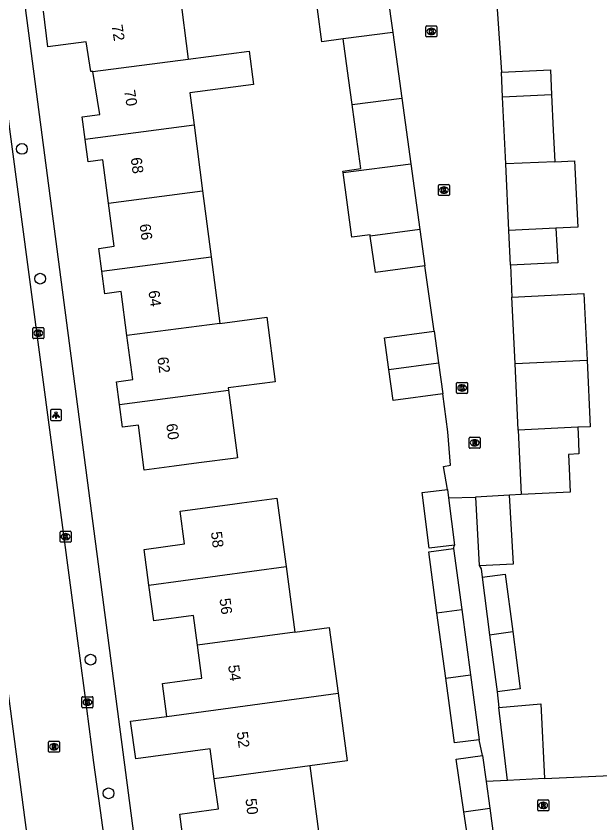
# Model space of a CAD drawing. Extents: x 161084 to 161928, y 385355 to 386522.
# Drawn here: x 161239.4 to 161292.4, y 386038.7 to 386112 of the extents above; entities that cross this region are included whole.
import ezdxf

# ---------------------------------------------------------------- set-up
doc = ezdxf.new("R2010")
doc.units = 0
for name, color, linetype in [('IMGEO_Boom', 7, 'Continuous'), ('IMGEO_Kolk', 7, 'Continuous'), ('IMGEO_Lichtpunt', 7, 'Continuous'), ('IMGEO_Pand', 7, 'Continuous'), ('IMGEO_Pand_nummerreeks', 7, 'Continuous'), ('IMGEO_Rijbaan_lokaal_open', 7, 'Continuous'), ('IMGEO_Rioolput', 7, 'Continuous'), ('IMGEO_Voetpad_open', 7, 'Continuous')]:
    doc.layers.add(name, color=color, linetype=linetype)

msp = doc.modelspace()

# ---------------------------------------------------------------- linework, layer by layer
at = {"layer": 'IMGEO_Boom'}
for centre in [(161239.881, 386099.938), (161241.543, 386088.142), (161246.128, 386053.505), (161247.762, 386041.354)]:
    msp.add_circle(centre, 0.489, dxfattribs=at)
at = {"layer": 'IMGEO_Kolk'}
for p, q in [((161276.692, 386111.123), (161277.544, 386111.123)), ((161276.617, 386110.197), (161276.617, 386111.049)), ((161277.128, 386110.343), (161277.103, 386110.343)), ((161277.105, 386110.903), (161277.13, 386110.903)), ((161277.618, 386111.049), (161277.618, 386110.197)), ((161277.544, 386110.123), (161276.692, 386110.123)), ((161277.763, 386095.772), (161277.763, 386096.624)), ((161277.838, 386096.698), (161278.69, 386096.698)), ((161278.251, 386096.478), (161278.276, 386096.478)), ((161278.764, 386096.624), (161278.764, 386095.772)), ((161278.69, 386095.698), (161277.838, 386095.698)), ((161278.274, 386095.918), (161278.249, 386095.918)), ((161240.877, 386082.763), (161240.877, 386083.615)), ((161240.952, 386083.689), (161241.804, 386083.689)), ((161241.365, 386083.469), (161241.39, 386083.469)), ((161241.878, 386083.615), (161241.878, 386082.763)), ((161241.804, 386082.689), (161240.952, 386082.689)), ((161241.388, 386082.909), (161241.363, 386082.909)), ((161279.415, 386077.779), (161279.415, 386078.631)), ((161279.49, 386078.705), (161280.342, 386078.705)), ((161279.903, 386078.485), (161279.928, 386078.485)), ((161280.416, 386078.631), (161280.416, 386077.779)), ((161280.342, 386077.705), (161279.49, 386077.705)), ((161279.926, 386077.925), (161279.901, 386077.925)), ((161243.352, 386064.258), (161243.352, 386065.11)), ((161243.427, 386065.184), (161244.279, 386065.184)), ((161243.84, 386064.964), (161243.865, 386064.964)), ((161244.353, 386065.11), (161244.353, 386064.258)), ((161244.279, 386064.184), (161243.427, 386064.184)), ((161243.863, 386064.404), (161243.838, 386064.404)), ((161245.342, 386049.207), (161245.342, 386050.059)), ((161245.417, 386050.133), (161246.269, 386050.133)), ((161245.83, 386049.913), (161245.855, 386049.913)), ((161246.343, 386050.059), (161246.343, 386049.207)), ((161246.269, 386049.133), (161245.417, 386049.133)), ((161245.853, 386049.353), (161245.828, 386049.353))]:
    msp.add_line(p, q, dxfattribs=at)
for points in [[(161276.692, 386111.123), (161277.544, 386111.123)], [(161276.617, 386110.197), (161276.617, 386111.049)], [(161276.938, 386110.823), (161277.061, 386110.823), (161277.061, 386110.672), (161277.191, 386110.823), (161277.355, 386110.823), (161277.209, 386110.672), (161277.362, 386110.423), (161277.21, 386110.423), (161277.125, 386110.587), (161277.061, 386110.52), (161277.061, 386110.423), (161276.938, 386110.423), (161276.938, 386110.823)], [(161277.618, 386111.049), (161277.618, 386110.197)], [(161277.544, 386110.123), (161276.692, 386110.123)], [(161277.763, 386095.772), (161277.763, 386096.624)], [(161277.838, 386096.698), (161278.69, 386096.698)], [(161278.764, 386096.624), (161278.764, 386095.772)], [(161278.69, 386095.698), (161277.838, 386095.698)], [(161278.084, 386096.398), (161278.207, 386096.398), (161278.207, 386096.247), (161278.337, 386096.398), (161278.501, 386096.398), (161278.355, 386096.247), (161278.508, 386095.998), (161278.356, 386095.998), (161278.271, 386096.162), (161278.207, 386096.095), (161278.207, 386095.998), (161278.084, 386095.998), (161278.084, 386096.398)], [(161240.877, 386082.763), (161240.877, 386083.615)], [(161240.952, 386083.689), (161241.804, 386083.689)], [(161241.198, 386083.389), (161241.321, 386083.389), (161241.321, 386083.238), (161241.451, 386083.389), (161241.615, 386083.389), (161241.469, 386083.238), (161241.622, 386082.989), (161241.47, 386082.989), (161241.385, 386083.153), (161241.321, 386083.086), (161241.321, 386082.989), (161241.198, 386082.989), (161241.198, 386083.389)], [(161241.878, 386083.615), (161241.878, 386082.763)], [(161241.804, 386082.689), (161240.952, 386082.689)], [(161279.415, 386077.779), (161279.415, 386078.631)], [(161279.49, 386078.705), (161280.342, 386078.705)], [(161279.736, 386078.405), (161279.859, 386078.405), (161279.859, 386078.254), (161279.989, 386078.405), (161280.153, 386078.405), (161280.007, 386078.254), (161280.16, 386078.005), (161280.008, 386078.005), (161279.923, 386078.169), (161279.859, 386078.102), (161279.859, 386078.005), (161279.736, 386078.005), (161279.736, 386078.405)], [(161280.416, 386078.631), (161280.416, 386077.779)], [(161280.342, 386077.705), (161279.49, 386077.705)], [(161243.352, 386064.258), (161243.352, 386065.11)], [(161243.427, 386065.184), (161244.279, 386065.184)], [(161243.673, 386064.884), (161243.796, 386064.884), (161243.796, 386064.733), (161243.926, 386064.884), (161244.09, 386064.884), (161243.944, 386064.733), (161244.097, 386064.484), (161243.945, 386064.484), (161243.86, 386064.648), (161243.796, 386064.581), (161243.796, 386064.484), (161243.673, 386064.484), (161243.673, 386064.884)], [(161244.353, 386065.11), (161244.353, 386064.258)], [(161244.279, 386064.184), (161243.427, 386064.184)], [(161245.342, 386049.207), (161245.342, 386050.059)], [(161245.417, 386050.133), (161246.269, 386050.133)], [(161245.663, 386049.833), (161245.786, 386049.833), (161245.786, 386049.682), (161245.916, 386049.833), (161246.08, 386049.833), (161245.934, 386049.682), (161246.087, 386049.433), (161245.935, 386049.433), (161245.85, 386049.597), (161245.786, 386049.53), (161245.786, 386049.433), (161245.663, 386049.433), (161245.663, 386049.833)], [(161246.343, 386050.059), (161246.343, 386049.207)], [(161246.269, 386049.133), (161245.417, 386049.133)]]:
    msp.add_lwpolyline(points, dxfattribs=at)
for centre, start, end in [((161276.694, 386111.047), 91.55205, 178.44795), ((161276.694, 386111.047), 91.55205, 178.44795), ((161277.542, 386111.047), 1.55205, 88.44795), ((161277.542, 386111.047), 1.55205, 88.44795), ((161276.694, 386110.199), 181.55205, 268.44795), ((161276.694, 386110.199), 181.55205, 268.44795), ((161277.542, 386110.199), 271.55205, 358.44795), ((161277.542, 386110.199), 271.55205, 358.44795), ((161277.84, 386096.622), 91.55205, 178.44795), ((161277.84, 386096.622), 91.55205, 178.44795), ((161278.688, 386096.622), 1.55205, 88.44795), ((161278.688, 386096.622), 1.55205, 88.44795), ((161277.84, 386095.774), 181.55205, 268.44795), ((161277.84, 386095.774), 181.55205, 268.44795), ((161278.688, 386095.774), 271.55205, 358.44795), ((161278.688, 386095.774), 271.55205, 358.44795), ((161240.954, 386083.613), 91.55205, 178.44795), ((161240.954, 386083.613), 91.55205, 178.44795), ((161241.802, 386083.613), 1.55205, 88.44795), ((161241.802, 386083.613), 1.55205, 88.44795), ((161240.954, 386082.765), 181.55205, 268.44795), ((161240.954, 386082.765), 181.55205, 268.44795), ((161241.802, 386082.765), 271.55205, 358.44795), ((161241.802, 386082.765), 271.55205, 358.44795), ((161279.492, 386078.629), 91.55205, 178.44795), ((161279.492, 386078.629), 91.55205, 178.44795), ((161280.34, 386078.629), 1.55205, 88.44795), ((161280.34, 386078.629), 1.55205, 88.44795), ((161279.492, 386077.781), 181.55205, 268.44795), ((161279.492, 386077.781), 181.55205, 268.44795), ((161280.34, 386077.781), 271.55205, 358.44795), ((161280.34, 386077.781), 271.55205, 358.44795), ((161243.429, 386065.108), 91.55205, 178.44795), ((161243.429, 386065.108), 91.55205, 178.44795), ((161244.277, 386065.108), 1.55205, 88.44795), ((161244.277, 386065.108), 1.55205, 88.44795), ((161243.429, 386064.26), 181.55205, 268.44795), ((161243.429, 386064.26), 181.55205, 268.44795), ((161244.277, 386064.26), 271.55205, 358.44795), ((161244.277, 386064.26), 271.55205, 358.44795), ((161245.419, 386050.057), 91.55205, 178.44795), ((161245.419, 386050.057), 91.55205, 178.44795), ((161246.267, 386050.057), 1.55205, 88.44795), ((161246.267, 386050.057), 1.55205, 88.44795), ((161245.419, 386049.209), 181.55205, 268.44795), ((161245.419, 386049.209), 181.55205, 268.44795), ((161246.267, 386049.209), 271.55205, 358.44795), ((161246.267, 386049.209), 271.55205, 358.44795)]:
    msp.add_arc(centre, 0.0765, start, end, dxfattribs=at)
for centre, major_axis, ratio, start_param, end_param in [((161277.104, 386110.623), (-0.387, 0.002), 0.722429, 4.712389, 7.853982), ((161277.129, 386110.623), (-0.39, 0.002), 0.717154, 1.570796, 4.712389), ((161278.25, 386096.198), (-0.387, 0.002), 0.722429, 4.712389, 7.853982), ((161278.275, 386096.198), (-0.39, 0.002), 0.717154, 1.570796, 4.712389), ((161241.364, 386083.189), (-0.387, 0.002), 0.722429, 4.712389, 7.853982), ((161241.389, 386083.189), (-0.39, 0.002), 0.717154, 1.570796, 4.712389), ((161279.902, 386078.205), (-0.387, 0.002), 0.722429, 4.712389, 7.853982), ((161279.927, 386078.205), (-0.39, 0.002), 0.717154, 1.570796, 4.712389), ((161243.839, 386064.684), (-0.387, 0.002), 0.722429, 4.712389, 7.853982), ((161243.864, 386064.684), (-0.39, 0.002), 0.717154, 1.570796, 4.712389), ((161245.829, 386049.633), (-0.387, 0.002), 0.722429, 4.712389, 7.853982), ((161245.854, 386049.633), (-0.39, 0.002), 0.717154, 1.570796, 4.712389)]:
    msp.add_ellipse(centre, major_axis=major_axis, ratio=ratio, start_param=start_param, end_param=end_param, dxfattribs=at)
at = {"layer": 'IMGEO_Lichtpunt'}
for p, q in [((161242.475, 386076.141), (161242.475, 386075.334)), ((161242.475, 386076.141), (161242.475, 386075.334)), ((161243.377, 386076.236), (161242.569, 386076.236)), ((161243.377, 386076.236), (161242.569, 386076.236)), ((161243.471, 386075.334), (161243.471, 386076.141)), ((161243.471, 386075.334), (161243.471, 386076.141)), ((161242.569, 386075.24), (161243.377, 386075.24)), ((161242.569, 386075.24), (161243.377, 386075.24))]:
    msp.add_line(p, q, dxfattribs=at)
for points in [[(161242.849, 386075.805), (161242.888, 386075.777), (161242.7, 386075.515), (161242.662, 386075.542), (161242.849, 386075.805)], [(161242.951, 386075.757), (161242.998, 386075.757), (161242.998, 386075.435), (161242.951, 386075.435), (161242.951, 386075.757)], [(161243.061, 386075.777), (161243.099, 386075.804), (161243.286, 386075.542), (161243.247, 386075.514), (161243.061, 386075.777)]]:
    msp.add_lwpolyline(points, dxfattribs=at)
msp.add_circle((161242.974, 386075.939), 0.0994, dxfattribs=at)
for centre, start, end in [((161242.569, 386076.141), 90, 180), ((161242.569, 386076.141), 90, 180), ((161243.377, 386076.141), 0, 90), ((161243.377, 386076.141), 0, 90), ((161242.569, 386075.334), 180, 270), ((161242.569, 386075.334), 180, 270), ((161243.377, 386075.334), 270, 0), ((161243.377, 386075.334), 270, 360)]:
    msp.add_arc(centre, 0.0946, start, end, dxfattribs=at)
at = {"layer": 'IMGEO_Pand'}
for points in [[(161272.778, 386116.48), (161273.124, 386113.984), (161273.603, 386110.526)], [(161269.087, 386109.933), (161267.146, 386109.681), (161266.372, 386115.646)], [(161254.234, 386114.065), (161255.011, 386108.105)], [(161246.334, 386106.975), (161246.15, 386106.977), (161245.713, 386109.678), (161242.252, 386109.227), (161241.832, 386112.45)], [(161273.603, 386110.526), (161269.087, 386109.933)], [(161273.603, 386110.526), (161274.429, 386104.558)], [(161269.913, 386103.97), (161269.58, 386106.378), (161269.087, 386109.933)], [(161255.011, 386108.105), (161260.555, 386108.828), (161260.952, 386105.784), (161255.151, 386105.028), (161255.533, 386102.097)], [(161246.334, 386106.975), (161255.011, 386108.105)], [(161245.629, 386100.807), (161245.358, 386102.86), (161246.965, 386103.072), (161246.334, 386106.975)], [(161283.492, 386106.92), (161287.952, 386107.128), (161288.058, 386104.844)], [(161283.599, 386104.63), (161283.492, 386106.92)], [(161269.913, 386103.97), (161274.429, 386104.558)], [(161274.429, 386104.558), (161275.255, 386098.592)], [(161288.058, 386104.844), (161283.599, 386104.63)], [(161283.881, 386098.577), (161283.599, 386104.63)], [(161288.058, 386104.844), (161288.208, 386101.632), (161288.342, 386098.766)], [(161269.083, 386097.788), (161269.065, 386097.922), (161270.719, 386098.151), (161270.348, 386100.831), (161269.913, 386103.97)], [(161255.533, 386102.097), (161245.629, 386100.807)], [(161255.533, 386102.097), (161256.312, 386096.124)], [(161247.763, 386095.01), (161247.247, 386098.933), (161245.899, 386098.755), (161245.629, 386100.807)], [(161288.342, 386098.766), (161283.881, 386098.577)], [(161288.342, 386098.766), (161290.147, 386098.851), (161290.429, 386092.822), (161288.438, 386092.728)], [(161269.083, 386097.788), (161275.255, 386098.592)], [(161275.255, 386098.592), (161276.084, 386092.604)], [(161284.163, 386092.522), (161283.881, 386098.577)], [(161271.568, 386092.015), (161271.552, 386092.131), (161269.897, 386091.902), (161269.083, 386097.788)], [(161247.763, 386095.01), (161256.312, 386096.124)], [(161256.312, 386096.124), (161257.094, 386090.131)], [(161247.14, 386088.835), (161246.868, 386090.9), (161248.28, 386091.086), (161247.763, 386095.01)], [(161276.084, 386092.604), (161271.568, 386092.015)], [(161276.539, 386089.321), (161272.027, 386088.696), (161271.568, 386092.015)], [(161276.084, 386092.604), (161276.539, 386089.321)], [(161288.438, 386092.728), (161284.163, 386092.522)], [(161284.31, 386089.371), (161284.163, 386092.522)], [(161288.438, 386092.728), (161288.611, 386089.572), (161284.31, 386089.371)], [(161247.14, 386088.835), (161257.094, 386090.131)], [(161257.094, 386090.131), (161257.884, 386084.073)], [(161249.433, 386082.972), (161248.907, 386086.969), (161247.412, 386086.772), (161247.14, 386088.835)], [(161284.446, 386086.467), (161290.994, 386086.782), (161291.277, 386080.73)], [(161284.728, 386080.415), (161284.446, 386086.467)], [(161257.884, 386084.073), (161249.433, 386082.972)], [(161257.884, 386084.073), (161262.154, 386084.629), (161262.918, 386078.769), (161258.648, 386078.213), (161258.676, 386077.995)], [(161273.246, 386079.893), (161272.85, 386082.753), (161277.362, 386083.378)], [(161277.362, 386083.378), (161277.763, 386080.481)], [(161248.748, 386076.702), (161248.475, 386078.777), (161249.96, 386078.973), (161249.433, 386082.972)], [(161273.246, 386079.893), (161277.763, 386080.481)], [(161277.763, 386080.481), (161278.151, 386077.682)], [(161284.728, 386080.415), (161291.277, 386080.73)], [(161285.01, 386074.36), (161284.728, 386080.415)], [(161291.277, 386080.73), (161291.559, 386074.686), (161290.428, 386074.633)], [(161278.151, 386077.682), (161273.639, 386077.057), (161273.246, 386079.893)], [(161258.676, 386077.995), (161259.477, 386071.853), (161259.329, 386071.834), (161255.971, 386071.391), (161253.721, 386071.095), (161251.013, 386070.738), (161250.475, 386074.823), (161249.021, 386074.631), (161248.748, 386076.702)], [(161248.748, 386076.702), (161258.676, 386077.995)], [(161290.428, 386074.633), (161285.01, 386074.36)], [(161290.428, 386074.633), (161290.488, 386073.336), (161290.54, 386072.214), (161289.583, 386072.169), (161289.643, 386070.881), (161289.743, 386068.738), (161285.282, 386068.531)], [(161285.01, 386074.36), (161285.282, 386068.531)], [(161279.211, 386063.925), (161276.905, 386063.638), (161276.275, 386068.687), (161278.582, 386068.975)], [(161278.582, 386068.975), (161278.677, 386068.212)], [(161251.431, 386060.288), (161250.992, 386063.532), (161254.676, 386064.03), (161254.276, 386066.991), (161259.231, 386067.661), (161259.881, 386067.749), (161263.06, 386068.178), (161263.899, 386061.974)], [(161278.677, 386068.212), (161279.211, 386063.925)], [(161284.227, 386068.47), (161281.132, 386068.291)], [(161281.132, 386068.291), (161281.48, 386062.051)], [(161281.48, 386062.051), (161284.575, 386062.224), (161284.227, 386068.47)], [(161277.627, 386057.765), (161276.888, 386063.303), (161279.145, 386063.604)], [(161279.145, 386063.604), (161279.884, 386058.07)], [(161251.431, 386060.288), (161263.899, 386061.974)], [(161263.899, 386061.974), (161264.704, 386056.018)], [(161281.736, 386060.99), (161283.842, 386061.262), (161284.514, 386056.051)], [(161281.736, 386060.99), (161282.417, 386055.772)], [(161255.84, 386054.82), (161255.473, 386057.533), (161251.869, 386057.046), (161251.431, 386060.288)], [(161277.627, 386057.765), (161279.884, 386058.07)], [(161278.422, 386051.81), (161277.627, 386057.765)], [(161279.884, 386058.07), (161280.679, 386052.119)], [(161264.704, 386056.018), (161267.824, 386056.44), (161268.63, 386050.472)], [(161264.704, 386056.018), (161255.84, 386054.82)], [(161282.417, 386055.772), (161284.514, 386056.051)], [(161282.417, 386055.772), (161283.096, 386050.568)], [(161284.514, 386056.051), (161285.185, 386050.841), (161283.096, 386050.568)], [(161253.066, 386048.345), (161252.663, 386051.325), (161256.247, 386051.809), (161255.84, 386054.82)], [(161278.422, 386051.81), (161280.679, 386052.119)], [(161281.465, 386046.228), (161279.208, 386045.927), (161278.422, 386051.81)], [(161280.679, 386052.119), (161281.465, 386046.228)], [(161253.066, 386048.345), (161268.63, 386050.472)], [(161268.63, 386050.472), (161269.464, 386044.302), (161266.064, 386043.842)], [(161283.262, 386049.155), (161287.072, 386049.494), (161287.408, 386042.685)], [(161284.04, 386042.529), (161283.262, 386049.155)], [(161257.377, 386042.668), (161257.009, 386045.389), (161250.227, 386044.473), (161249.764, 386047.898), (161253.066, 386048.345)], [(161280.085, 386039.681), (161279.389, 386044.456), (161281.766, 386044.803)], [(161281.766, 386044.803), (161282.09, 386042.439)], [(161266.064, 386043.842), (161257.377, 386042.668)], [(161266.064, 386043.842), (161266.868, 386037.893)], [(161254.682, 386036.245), (161254.246, 386039.47), (161257.745, 386039.943), (161257.377, 386042.668)], [(161282.09, 386042.439), (161282.425, 386039.997)], [(161287.408, 386042.685), (161284.04, 386042.529)], [(161280.085, 386039.681), (161282.425, 386039.997)], [(161282.425, 386039.997), (161283.083, 386035.197)], [(161283.083, 386035.197), (161280.787, 386034.862), (161280.085, 386039.681)]]:
    msp.add_lwpolyline(points, dxfattribs=at)
at = {"layer": 'IMGEO_Rijbaan_lokaal_open'}
for points in [[(161249.06, 386024.426), (161247.627, 386035.348), (161247.158, 386038.91), (161246.418, 386044.153), (161245.561, 386050.7), (161244.91, 386055.679), (161244.435, 386059.357), (161238.791, 386101.741), (161237.904, 386108.656), (161237.062, 386115.21), (161235.904, 386124.085), (161235.446, 386127.639), (161233.045, 386146.313)], [(161229.8, 386117.181), (161231.888, 386101.189), (161232.965, 386093.061), (161233.963, 386085.526), (161235.806, 386071.61), (161236.296, 386067.915), (161242.179, 386023.509)], [(161282.969, 386114.42), (161283.492, 386106.92)], [(161277.362, 386083.378), (161276.539, 386089.321)], [(161284.31, 386089.371), (161284.446, 386086.467)], [(161278.582, 386068.975), (161278.226, 386071.079), (161278.867, 386071.181), (161278.631, 386074.215), (161278.151, 386077.682)], [(161278.677, 386068.212), (161281.132, 386068.291)], [(161285.282, 386068.531), (161284.227, 386068.47)], [(161287.408, 386042.685), (161317.411, 386044.073)], [(161284.04, 386042.529), (161282.09, 386042.439)]]:
    msp.add_lwpolyline(points, dxfattribs=at)
at = {"layer": 'IMGEO_Rioolput'}
for p, q in [((161280.637, 386073.722), (161281.489, 386073.722)), ((161280.562, 386072.796), (161280.562, 386073.648)), ((161281.073, 386072.942), (161281.048, 386072.942)), ((161281.05, 386073.502), (161281.075, 386073.502)), ((161281.563, 386073.648), (161281.563, 386072.796)), ((161281.489, 386072.722), (161280.637, 386072.722)), ((161242.303, 386045.162), (161242.303, 386046.014)), ((161242.378, 386046.088), (161243.23, 386046.088)), ((161242.791, 386045.868), (161242.816, 386045.868)), ((161243.304, 386046.014), (161243.304, 386045.162)), ((161243.23, 386045.088), (161242.378, 386045.088)), ((161242.814, 386045.308), (161242.789, 386045.308)), ((161286.789, 386039.831), (161286.789, 386040.683)), ((161286.864, 386040.757), (161287.716, 386040.757)), ((161287.79, 386040.683), (161287.79, 386039.831)), ((161287.3, 386039.977), (161287.275, 386039.977)), ((161287.277, 386040.537), (161287.302, 386040.537)), ((161287.716, 386039.757), (161286.864, 386039.757))]:
    msp.add_line(p, q, dxfattribs=at)
for points in [[(161280.637, 386073.722), (161281.489, 386073.722)], [(161280.562, 386072.796), (161280.562, 386073.648)], [(161281.151, 386073.42), (161280.899, 386073.422), (161280.899, 386073.022)], [(161280.899, 386073.022), (161281.023, 386073.022), (161281.023, 386073.184), (161281.034, 386073.184)], [(161281.077, 386073.341), (161281.023, 386073.341), (161281.023, 386073.26)], [(161281.023, 386073.26), (161281.075, 386073.26)], [(161281.081, 386073.155), (161281.152, 386073.022), (161281.292, 386073.022), (161281.227, 386073.148)], [(161281.563, 386073.648), (161281.563, 386072.796)], [(161281.489, 386072.722), (161280.637, 386072.722)], [(161242.303, 386045.162), (161242.303, 386046.014)], [(161242.378, 386046.088), (161243.23, 386046.088)], [(161243.304, 386046.014), (161243.304, 386045.162)], [(161243.23, 386045.088), (161242.378, 386045.088)], [(161242.892, 386045.786), (161242.64, 386045.788), (161242.64, 386045.388)], [(161242.64, 386045.388), (161242.764, 386045.388), (161242.764, 386045.55), (161242.775, 386045.55)], [(161242.818, 386045.707), (161242.764, 386045.707), (161242.764, 386045.626)], [(161242.764, 386045.626), (161242.816, 386045.626)], [(161242.822, 386045.521), (161242.893, 386045.388), (161243.033, 386045.388), (161242.968, 386045.514)], [(161286.789, 386039.831), (161286.789, 386040.683)], [(161286.864, 386040.757), (161287.716, 386040.757)], [(161287.79, 386040.683), (161287.79, 386039.831)], [(161287.378, 386040.455), (161287.126, 386040.457), (161287.126, 386040.057)], [(161287.126, 386040.057), (161287.25, 386040.057), (161287.25, 386040.219), (161287.261, 386040.219)], [(161287.304, 386040.376), (161287.25, 386040.376), (161287.25, 386040.295)], [(161287.25, 386040.295), (161287.302, 386040.295)], [(161287.308, 386040.19), (161287.379, 386040.057), (161287.519, 386040.057), (161287.454, 386040.183)], [(161287.716, 386039.757), (161286.864, 386039.757)]]:
    msp.add_lwpolyline(points, dxfattribs=at)
for centre, radius, start, end in [((161280.639, 386073.646), 0.0765, 91.55205, 178.44795), ((161280.639, 386073.646), 0.0765, 91.55205, 178.44795), ((161281.487, 386073.646), 0.0765, 1.55205, 88.44795), ((161281.487, 386073.646), 0.0765, 1.55205, 88.44795), ((161281.033, 386073.131), 0.0533, 26.02933, 88.69889), ((161281.059, 386073.449), 0.19, 274.7715, 282.96867), ((161281.083, 386073.245), 0.0964, 77.00612, 93.18647), ((161281.097, 386073.302), 0.0378, 276.66336, 79.67722), ((161281.15, 386073.31), 0.109, 350.36119, 89.41601), ((161281.148, 386073.31), 0.112, 277.58423, 350.98172), ((161281.132, 386073.095), 0.108, 29.51342, 73.79051), ((161280.639, 386072.798), 0.0765, 181.55205, 268.44795), ((161280.639, 386072.798), 0.0765, 181.55205, 268.44795), ((161281.487, 386072.798), 0.0765, 271.55205, 358.44795), ((161281.487, 386072.798), 0.0765, 271.55205, 358.44795), ((161242.38, 386046.012), 0.0765, 91.55205, 178.44795), ((161242.38, 386046.012), 0.0765, 91.55205, 178.44795), ((161243.228, 386046.012), 0.0765, 1.55205, 88.44795), ((161243.228, 386046.012), 0.0765, 1.55205, 88.44795), ((161242.38, 386045.164), 0.0765, 181.55205, 268.44795), ((161242.38, 386045.164), 0.0765, 181.55205, 268.44795), ((161242.774, 386045.497), 0.0533, 26.02933, 88.69889), ((161242.8, 386045.815), 0.19, 274.7715, 282.96867), ((161242.824, 386045.611), 0.0964, 77.00612, 93.18647), ((161242.838, 386045.668), 0.0378, 276.66336, 79.67722), ((161242.891, 386045.676), 0.109, 350.36119, 89.41601), ((161242.889, 386045.676), 0.112, 277.58423, 350.98172), ((161242.873, 386045.461), 0.108, 29.51342, 73.79051), ((161243.228, 386045.164), 0.0765, 271.55205, 358.44795), ((161243.228, 386045.164), 0.0765, 271.55205, 358.44795), ((161286.866, 386040.681), 0.0765, 91.55205, 178.44795), ((161286.866, 386040.681), 0.0765, 91.55205, 178.44795), ((161287.714, 386040.681), 0.0765, 1.55205, 88.44795), ((161287.714, 386040.681), 0.0765, 1.55205, 88.44795), ((161287.26, 386040.166), 0.0533, 26.02933, 88.69889), ((161287.286, 386040.484), 0.19, 274.7715, 282.96867), ((161287.31, 386040.28), 0.0964, 77.00612, 93.18647), ((161287.324, 386040.337), 0.0378, 276.66336, 79.67722), ((161287.377, 386040.345), 0.109, 350.36119, 89.41601), ((161287.375, 386040.345), 0.112, 277.58423, 350.98172), ((161287.359, 386040.13), 0.108, 29.51342, 73.79051), ((161286.866, 386039.833), 0.0765, 181.55205, 268.44795), ((161286.866, 386039.833), 0.0765, 181.55205, 268.44795), ((161287.714, 386039.833), 0.0765, 271.55205, 358.44795), ((161287.714, 386039.833), 0.0765, 271.55205, 358.44795)]:
    msp.add_arc(centre, radius, start, end, dxfattribs=at)
for centre, major_axis, ratio, start_param, end_param in [((161281.049, 386073.222), (-0.387, 0.002), 0.722429, 4.712389, 7.853982), ((161281.074, 386073.222), (-0.39, 0.002), 0.717154, 1.570796, 4.712389), ((161242.79, 386045.588), (-0.387, 0.002), 0.722429, 4.712389, 7.853982), ((161242.815, 386045.588), (-0.39, 0.002), 0.717154, 1.570796, 4.712389), ((161287.276, 386040.257), (-0.387, 0.002), 0.722429, 4.712389, 7.853982), ((161287.301, 386040.257), (-0.39, 0.002), 0.717154, 1.570796, 4.712389)]:
    msp.add_ellipse(centre, major_axis=major_axis, ratio=ratio, start_param=start_param, end_param=end_param, dxfattribs=at)
at = {"layer": 'IMGEO_Voetpad_open'}
for points in [[(161235.653, 386146.984), (161252.413, 386019.447), (161255.001, 386000), (161257.909, 385977.952)], [(161279.145, 386063.604), (161279.211, 386063.925)], [(161281.48, 386062.051), (161281.637, 386061.751), (161281.736, 386060.99)], [(161283.096, 386050.568), (161283.262, 386049.155)], [(161281.766, 386044.803), (161281.465, 386046.228)]]:
    msp.add_lwpolyline(points, dxfattribs=at)

# ---------------------------------------------------------------- texts
at = {"layer": 'IMGEO_Pand_nummerreeks'}
for s, rotation, p in [('72', 279.19035, (161248.028, 386111.153)), ('70', 279.18341, (161249.169, 386105.231)), ('68', 277.6006, (161249.769, 386099.108)), ('66', 277.6006, (161250.576, 386093.062)), ('64', 277.6006, (161251.384, 386087.013)), ('62', 277.60294, (161252.19, 386080.967)), ('60', 277.6006, (161252.998, 386074.912)), ('58', 277.3783, (161257.063, 386065.097)), ('56', 277.3783, (161257.847, 386059.034)), ('54', 277.3783, (161258.633, 386052.968)), ('52', 277.37949, (161259.417, 386046.905)), ('50', 277.37949, (161260.204, 386040.833))]:
    msp.add_text(s, height=1, rotation=rotation, dxfattribs=at).set_placement(p)

doc.saveas('drawing.dxf')
